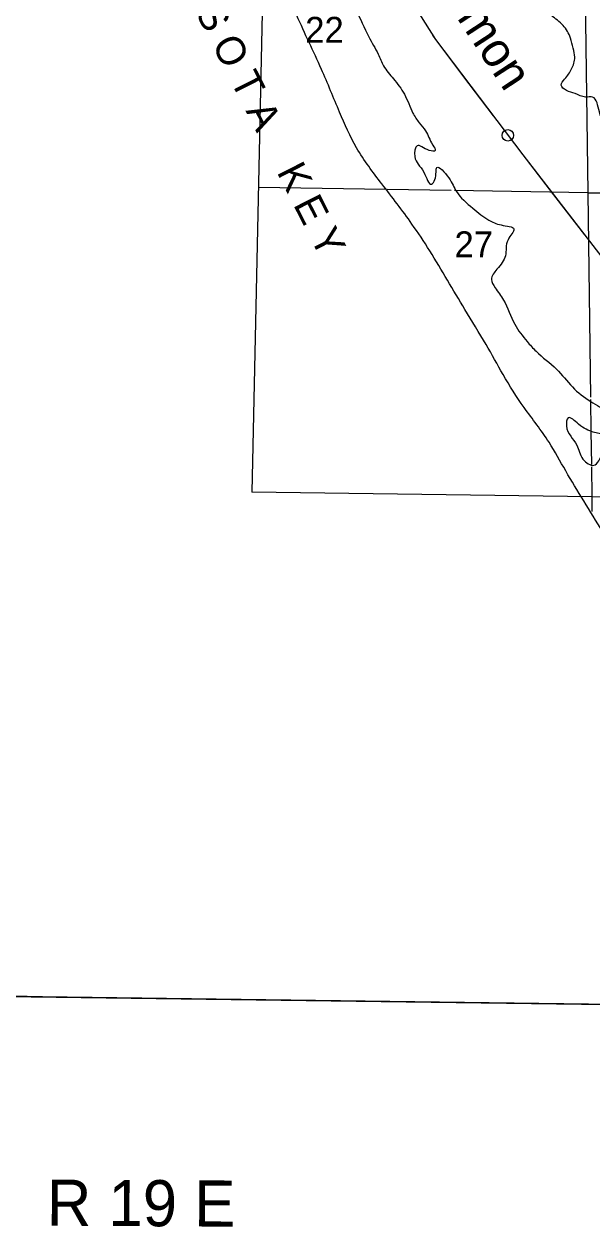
# Model space of a CAD drawing. Extents: x 408847 to 817539, y 923858 to 1151780.
# Drawn here: x 520932 to 530786, y 943095 to 963958 of the extents above; entities that cross this region are included whole.
import ezdxf

# ---------------------------------------------------------------- set-up
doc = ezdxf.new("R2010")
doc.units = 0
for name, color, linetype in [('Islands Coastal Text (Keys etc)', 7, 'Continuous'), ('Lakes and Ponds', 7, 'Continuous'), ('Level 12', 7, 'Continuous'), ('Level 42', 7, 'Continuous'), ('Level 43', 7, 'Continuous'), ('Narrow River Creek and Branch and Slough', 7, 'Continuous'), ('Section Lines', 7, 'Continuous')]:
    doc.layers.add(name, color=color, linetype=linetype)

msp = doc.modelspace()

# ---------------------------------------------------------------- linework, layer by layer
at = {"layer": 'Lakes and Ponds'}
msp.add_lwpolyline([(445956, 1114155), (440647, 1114276), (440664, 1103689), (442716, 1098915), (449861, 1083737), (453115, 1077012), (458491, 1066040), (462948, 1057545), (468536, 1049743), (472498, 1043513), (478122, 1032540), (482861, 1022317), (486681, 1012194), (492199, 996456), (497292, 983006), (501324, 975927), (505215, 969888), (509601, 961464), (511723, 957429), (515402, 947162), (533640, 946921), (535459, 946970)], dxfattribs=at)
for points in [[(534051, 959528), (533797, 959742), (533597, 959985), (533341, 960289), (533121, 960643), (532946, 960892), (532746, 961192), (532568, 961456), (532336, 961719), (532094, 961877), (531842, 961972), (531605, 962033), (531357, 962079), (531136, 962132), (530914, 962434), (530797, 962690), (530676, 962693), (530492, 962753), (530342, 962808), (530252, 962900), (530312, 963004), (530433, 963179), (530488, 963383), (530460, 963540), (530412, 963716), (530285, 963935), (530081, 964105), (529800, 964348), (529621, 964638), (529511, 964894), (529373, 965132), (529127, 965404), (528869, 965493), (528741, 965617), (528894, 965719), (529036, 965768), (529223, 965838), (529493, 965871), (529534, 965955), (529408, 966055), (529189, 966113), (529095, 965976), (528984, 965922), (528780, 965869), (528603, 965868), (528435, 965996), (528383, 966130), (528354, 966272), (528288, 966480), (528226, 966718), (528173, 966980), (528289, 966987), (528372, 967075), (528440, 967224), (528535, 967524), (528664, 967815), (528833, 967964), (529142, 968183), (529478, 968388), (529690, 968467), (529869, 968488), (529905, 968656), (529824, 968808), (529882, 968872), (529959, 968958), (530184, 969058), (530359, 968758), (530493, 968566), (530634, 968324), (530810, 968040), (530944, 967890), (530928, 967984), (530839, 968178), (530747, 968316), (530639, 968499), (530580, 968625), (530488, 968758), (530338, 968996), (530272, 969122), (530392, 969198), (530499, 969309), (530594, 969446)], [(523579, 969255), (523821, 968942), (524357, 968304), (524489, 968142), (524585, 968018), (524768, 967802), (524916, 967444), (525038, 967177), (525266, 967135), (525420, 967068), (525432, 966803), (525375, 966625), (525465, 966461), (525637, 966428), (525717, 966274), (525966, 965734), (526230, 965464), (526422, 965151), (526489, 964878), (526337, 964876), (526391, 964658), (526694, 964192), (526912, 963738), (527075, 963437), (527169, 963233), (527341, 963009), (527531, 962741), (527680, 962415), (527786, 962247), (527900, 962106), (528024, 961860), (528066, 961764), (527959, 961767), (527753, 961849), (527711, 961663), (527868, 961387), (528004, 961183), (528062, 961261), (528095, 961472), (528301, 961292), (528435, 961052), (528719, 960763), (528997, 960557), (529211, 960474), (529432, 960401), (529329, 960218), (529286, 959941), (529137, 959705), (529043, 959530), (529104, 959386), (529252, 959172), (529446, 958751), (529661, 958453), (529815, 958283), (530171, 957974), (530447, 957664), (530764, 957411), (531070, 957230), (531202, 957124), (531294, 956906), (531027, 956837), (530808, 956883), (530554, 957018), (530372, 957128), (530343, 956991), (530521, 956657), (530629, 956412), (530819, 956306), (530984, 956505), (531215, 956654), (531440, 956829), (531709, 957044), (531886, 957140), (532010, 956971), (532021, 956704), (532149, 956551), (532238, 956261), (532162, 956074), (532329, 955794), (532377, 955506), (532230, 955385), (531994, 955741), (531800, 955919), (531590, 956054), (531452, 956244), (531148, 956335), (531051, 956209), (531173, 955893), (531367, 955599), (531640, 955315), (531772, 955040), (531860, 954776), (532053, 954368), (532309, 953984), (532585, 953721), (532901, 953453), (533117, 953296)], [(533713, 950405), (533512, 950768), (533310, 951192), (533135, 951510), (532889, 951893), (532570, 952513), (532197, 953197), (531971, 953574), (531747, 953936), (531552, 954240), (531240, 954758), (530970, 955159), (530643, 955689), (530331, 956208), (530042, 956704), (529608, 957309), (529243, 957879), (528949, 958401), (528582, 959006), (527971, 960027), (527663, 960489), (527142, 961186), (526702, 961811), (526407, 962431), (526092, 963173), (525665, 964107), (525299, 964995), (524966, 965703), (524188, 966689), (523785, 967350), (523403, 968047), (523043, 968590), (522835, 969029)]]:
    msp.add_spline(points, degree=3, dxfattribs=at)
at = {"layer": 'Level 12'}
msp.add_circle((529327, 962028), 99.8, dxfattribs=at)
at = {"layer": 'Level 42'}
msp.add_lwpolyline([(532451, 946938), (521253, 947089), (515376, 947213), (513090, 953579), (511566, 957748), (509383, 961807), (508416, 963661), (505193, 969909), (503834, 972010), (500992, 976511), (499118, 979725), (497697, 982321), (497038, 983648), (495267, 988387), (492457, 995710), (491365, 998924), (488544, 1006981), (486526, 1012565), (483931, 1019412), (482647, 1022967), (480114, 1028262), (477993, 1032786)], dxfattribs=at)
at = {"layer": 'Narrow River Creek and Branch and Slough'}
for points in [[(527710, 964255), (528070, 963688), (529584, 961690), (531406, 959332), (533921, 956023), (535867, 953345), (536794, 951958), (538709, 949025), (539852, 947287)], [(528020, 963767), (528070, 963688), (528542, 963065)], [(528542, 963065), (529071, 962367)], [(529584, 961690), (530119, 960997)], [(530119, 960997), (530654, 960305)]]:
    msp.add_lwpolyline(points, dxfattribs=at)
at = {"layer": 'Section Lines'}
for p, q in [((530644, 966401), (530714, 961033)), ((525093, 965441), (524885, 955842)), ((527210, 961090), (524999, 961125)), ((528341, 961071), (527230, 961089)), ((530714, 961033), (528400, 961070)), ((530714, 961033), (530760, 957490)), ((530714, 961033), (535925, 960991)), ((530760, 957449), (530767, 956893)), ((530767, 956893), (530775, 956317)), ((530775, 956277), (530782, 955758)), ((530782, 955758), (524885, 955842)), ((531201, 955752), (530782, 955758)), ((530782, 955758), (530785, 955502))]:
    msp.add_line(p, q, dxfattribs=at)

# ---------------------------------------------------------------- texts
at = {"layer": 'Islands Coastal Text (Keys etc)'}
msp.add_text('M A N A S O T A    K E Y', height=500, rotation=296.95, dxfattribs=at).set_placement((522683, 966561))
at = {"layer": 'Level 42'}
msp.add_text('Lemon', height=600, rotation=303.1312, dxfattribs=at).set_placement((527945, 964817))
at = {"layer": 'Level 43'}
for s, height, rotation, p in [('22', 450, 0, (525810, 963633)), ('27', 450, 0, (528400, 959913)), ('R 19 E', 800, 359.6819, (521325, 943118))]:
    msp.add_text(s, height=height, rotation=rotation, dxfattribs=at).set_placement(p)

doc.saveas('drawing.dxf')
